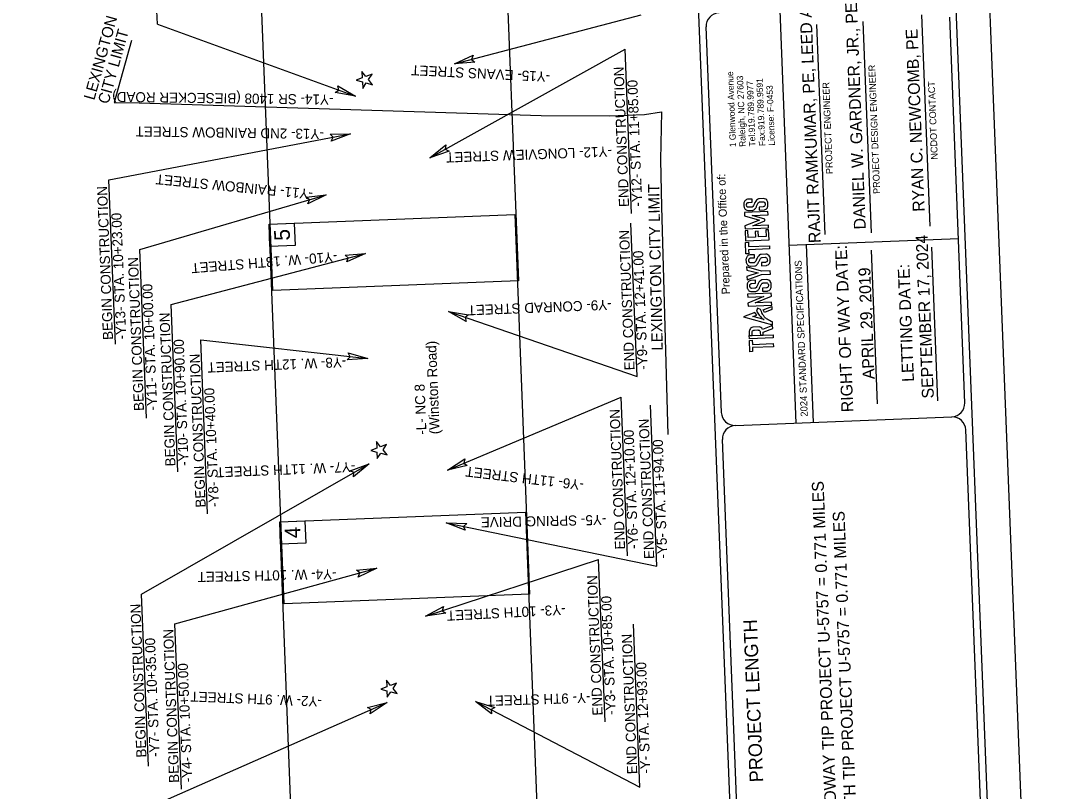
# Model space of a CAD drawing. Extents: x 1624323 to 1631382, y 753034 to 769560.
# Drawn here: x 1626744 to 1631382, y 761728 to 765176 of the extents above; entities that cross this region are included whole.
import ezdxf

# ---------------------------------------------------------------- set-up
doc = ezdxf.new("R2010")
doc.units = 0
for name, color, linetype in [('Old_Level_1', 7, 'Continuous'), ('Old_Level_2', 7, 'Continuous'), ('Prop Dimension', 7, 'Continuous'), ('Prop DSN Text', 7, 'Continuous'), ('Prop PHM City or Township Limit Line', 7, 'Continuous'), ('Prop RDY Traffic Signal CELL', 7, 'Continuous'), ('Prop Terminator CELL', 7, 'Continuous'), ('Sheet Data Field CELL', 7, 'Continuous'), ('Sheet Plot Border Outside CELL', 7, 'Continuous'), ('Sheet Title CELL', 7, 'Continuous')]:
    doc.layers.add(name, color=color, linetype=linetype)

msp = doc.modelspace()

# ---------------------------------------------------------------- linework, layer by layer
at = {"layer": 'Old_Level_1'}
for points in [[(1627871.9, 763968.6), (1627804.9, 765667.2), (1628904.1, 765710.6), (1628971.1, 764011.9)], [(1630017.6, 764363.7), (1630017, 764377.7), (1629996, 764376.8), (1629991.8, 764375.5), (1629988.3, 764373.6), (1629986, 764371.7), (1629984, 764369.4), (1629982.4, 764366.7), (1629981.4, 764364.1), (1629981.4, 764364.1), (1629980.3, 764361.3), (1629979.7, 764358.3), (1629979.3, 764356.3), (1629980, 764345.8), (1629980.6, 764342.6), (1629981.2, 764339.9), (1629982.8, 764337.1), (1629984.1, 764334.7), (1629986, 764332.4), (1629987.9, 764330.6), (1629990.2, 764329.2), (1629992.6, 764328.2), (1629996.9, 764326.8), (1630000, 764326.6), (1630019.2, 764327.4), (1630022, 764328.2), (1630025, 764329.7), (1630027.4, 764331.5), (1630029.2, 764333.4), (1630031.2, 764336.2), (1630033.2, 764339), (1630034.4, 764340.8), (1630035.7, 764343.8), (1630036.9, 764346.7), (1630038.4, 764349.2), (1630040, 764351.9), (1630041.5, 764355.1), (1630042.7, 764357.8), (1630044.5, 764360.5), (1630046.2, 764362.4), (1630047.6, 764364), (1630050.4, 764365), (1630052.2, 764365.7), (1630065.8, 764366), (1630068.7, 764365.1), (1630071.3, 764363.8), (1630073.2, 764361.8), (1630074.2, 764359.7), (1630074.7, 764357.7), (1630075.1, 764351.9), (1630074.6, 764349.9), (1630073.5, 764347.9), (1630072.4, 764345.8), (1630070.4, 764344.9), (1630068.5, 764344), (1630066.9, 764343.2), (1630048.1, 764342.3), (1630048.8, 764328.1), (1630071.2, 764329.3), (1630072.9, 764330.1), (1630078, 764331.9), (1630079.8, 764333), (1630081.6, 764334.6), (1630083.8, 764337), (1630084.9, 764338.9), (1630085.9, 764341.6), (1630086.2, 764342.5), (1630087.2, 764345.2), (1630087.4, 764348.4), (1630087.6, 764350.8), (1630086.7, 764363.8), (1630085.7, 764367.3), (1630083.3, 764372.2), (1630082.5, 764373.9), (1630077.5, 764377.4), (1630072.7, 764379.3), (1630068.4, 764380), (1630047.7, 764378.9), (1630044.8, 764378.7), (1630042.6, 764377.9), (1630040.5, 764376.6), (1630036, 764373.2), (1630032.8, 764368.8), (1630029.6, 764362.7), (1630027.1, 764358.1), (1630022.8, 764349.1), (1630019.6, 764344.4), (1630017.1, 764342.3), (1630015.4, 764341.8), (1630013.7, 764341.3), (1629999, 764340.9), (1629997.4, 764341.6), (1629995.8, 764342.3), (1629994.9, 764343.4), (1629993.6, 764344.7), (1629992.9, 764346.3), (1629992.2, 764347.8), (1629992.4, 764348.7), (1629991.9, 764348.8), (1629991.8, 764354.6), (1629992.4, 764356.3), (1629993, 764358), (1629993.6, 764359.7), (1629994.7, 764360.5), (1629996.3, 764361.7), (1629998, 764362.3), (1629999.6, 764362.9), (1630001.5, 764363)], [(1627922.1, 762567.4), (1627855.1, 764266), (1628954.3, 764309.4), (1629021.3, 762610.7)], [(1630049.2, 764283), (1629984.1, 764257.4), (1629985.2, 764244), (1630090.8, 764248.7), (1630090.2, 764261.5), (1630019.6, 764258.3), (1630073.2, 764280.2), (1630073, 764288.4), (1630017.1, 764304.8), (1630088, 764307.8), (1630087.4, 764321.6), (1629982.1, 764317.1), (1629982.7, 764303.2)], [(1627859.1, 764166.1), (1627855.1, 764266), (1627967.5, 764270.5), (1627971.5, 764170.6)], [(1629985.3, 764235.9), (1629987.1, 764191.2), (1630092.5, 764195.5), (1630090.7, 764240.6), (1630078.8, 764240.2), (1630080, 764209.7), (1630044.7, 764208.2), (1630043.6, 764233.7), (1630031.1, 764233.2), (1630032.1, 764207.5), (1629998.9, 764206.2), (1629997.7, 764236.5)], [(1629989.4, 764132.7), (1629987.4, 764183.8), (1629999.9, 764184.4), (1630000.7, 764165.5), (1630093.9, 764169.3), (1630094.5, 764155.1), (1630000.6, 764151.3), (1630001.4, 764133.4)], [(1630027.6, 764115.1), (1630027.1, 764129), (1630006, 764128.2), (1630001.8, 764126.8), (1629998.3, 764125), (1629996, 764123.1), (1629994, 764120.8), (1629992.4, 764118), (1629991.4, 764115.4), (1629991.4, 764115.4), (1629990.4, 764112.6), (1629989.8, 764109.7), (1629989.3, 764107.7), (1629990, 764097.1), (1629990.7, 764094), (1629991.2, 764091.2), (1629992.8, 764088.5), (1629994.2, 764086.1), (1629996, 764083.8), (1629998, 764082), (1630000.2, 764080.6), (1630002.7, 764079.5), (1630006.9, 764078.1), (1630010.1, 764078), (1630029.2, 764078.7), (1630032.1, 764079.5), (1630035, 764081), (1630037.4, 764082.9), (1630039.2, 764084.7), (1630041.2, 764087.5), (1630043.2, 764090.4), (1630044.5, 764092.1), (1630045.7, 764095.1), (1630047, 764098.1), (1630048.4, 764100.5), (1630050, 764103.2), (1630051.5, 764106.5), (1630052.7, 764109.2), (1630054.5, 764111.8), (1630056.2, 764113.8), (1630057.6, 764115.4), (1630060.5, 764116.4), (1630062.3, 764117), (1630075.8, 764117.3), (1630078.8, 764116.5), (1630081.4, 764115.1), (1630083.2, 764113.2), (1630084.3, 764111.1), (1630084.8, 764109), (1630085.1, 764103.2), (1630084.7, 764101.3), (1630083.6, 764099.2), (1630082.5, 764097.2), (1630080.5, 764096.3), (1630078.5, 764095.3), (1630076.9, 764094.6), (1630058.1, 764093.6), (1630058.8, 764079.5), (1630081.2, 764080.6), (1630082.9, 764081.4), (1630088.1, 764083.2), (1630089.8, 764084.4), (1630091.6, 764086), (1630093.8, 764088.4), (1630094.9, 764090.2), (1630095.9, 764092.9), (1630096.3, 764093.9), (1630097.3, 764096.5), (1630097.5, 764099.8), (1630097.6, 764102.2), (1630096.8, 764115.1), (1630095.8, 764118.7), (1630093.3, 764123.6), (1630092.5, 764125.2), (1630087.6, 764128.8), (1630082.7, 764130.6), (1630078.4, 764131.4), (1630057.7, 764130.3), (1630054.9, 764130.1), (1630052.6, 764129.2), (1630050.5, 764128), (1630046.1, 764124.5), (1630042.9, 764120.1), (1630039.6, 764114.1), (1630037.1, 764109.5), (1630032.8, 764100.5), (1630029.6, 764095.8), (1630027.1, 764093.7), (1630025.4, 764093.1), (1630023.7, 764092.6), (1630009, 764092.3), (1630007.5, 764093), (1630005.9, 764093.7), (1630004.9, 764094.7), (1630003.7, 764096.1), (1630003, 764097.6), (1630002.3, 764099.1), (1630002.4, 764100), (1630001.9, 764100.1), (1630001.8, 764105.9), (1630002.4, 764107.6), (1630003, 764109.3), (1630003.6, 764111), (1630004.7, 764111.9), (1630006.4, 764113), (1630008, 764113.7), (1630009.7, 764114.3), (1630011.5, 764114.3)], [(1629993.6, 764031.4), (1629994.2, 764016), (1630059.1, 764040.5), (1630098.7, 764042.2), (1630098, 764056.7), (1630058.8, 764054.9), (1629991.6, 764074.4), (1629992.7, 764059.4), (1630043.6, 764047.4)], [(1630032.2, 764001), (1630031.7, 764014.9), (1630010.6, 764014.1), (1630006.4, 764012.7), (1630002.9, 764010.9), (1630000.6, 764009), (1629998.6, 764006.7), (1629997, 764004), (1629996, 764001.3), (1629996, 764001.3), (1629995, 763998.5), (1629994.4, 763995.6), (1629994, 763993.6), (1629994.6, 763983), (1629995.3, 763979.9), (1629995.9, 763977.1), (1629997.4, 763974.4), (1629998.8, 763972), (1630000.6, 763969.7), (1630002.6, 763967.9), (1630004.8, 763966.5), (1630007.3, 763965.4), (1630011.5, 763964.1), (1630014.7, 763963.9), (1630033.8, 763964.6), (1630036.7, 763965.4), (1630039.6, 763966.9), (1630042, 763968.8), (1630043.8, 763970.7), (1630045.8, 763973.5), (1630047.8, 763976.3), (1630049.1, 763978.1), (1630050.3, 763981), (1630051.6, 763984), (1630053, 763986.4), (1630054.6, 763989.2), (1630056.1, 763992.4), (1630057.3, 763995.1), (1630059.1, 763997.8), (1630060.8, 763999.7), (1630062.2, 764001.3), (1630065.1, 764002.3), (1630066.9, 764002.9), (1630080.4, 764003.3), (1630083.4, 764002.4), (1630086, 764001), (1630087.8, 763999.1), (1630088.9, 763997), (1630089.4, 763995), (1630089.7, 763989.2), (1630089.3, 763987.2), (1630088.2, 763985.1), (1630087.1, 763983.1), (1630085.1, 763982.2), (1630083.1, 763981.2), (1630081.5, 763980.5), (1630062.7, 763979.5), (1630063.4, 763965.4), (1630085.8, 763966.5), (1630087.5, 763967.3), (1630092.7, 763969.2), (1630094.4, 763970.3), (1630096.3, 763971.9), (1630098.4, 763974.3), (1630099.5, 763976.2), (1630100.5, 763978.8), (1630100.9, 763979.8), (1630101.9, 763982.5), (1630102.1, 763985.7), (1630102.2, 763988.1), (1630101.4, 764001), (1630100.4, 764004.6), (1630097.9, 764009.5), (1630097.1, 764011.1), (1630092.2, 764014.7), (1630087.3, 764016.5), (1630083, 764017.3), (1630062.3, 764016.2), (1630059.5, 764016), (1630057.2, 764015.1), (1630055.1, 764013.9), (1630050.7, 764010.5), (1630047.5, 764006), (1630044.2, 764000), (1630041.7, 763995.4), (1630037.4, 763986.4), (1630034.2, 763981.7), (1630031.7, 763979.6), (1630030, 763979.1), (1630028.3, 763978.5), (1630013.6, 763978.2), (1630012.1, 763978.9), (1630010.5, 763979.6), (1630009.5, 763980.6), (1630008.3, 763982), (1630007.6, 763983.5), (1630006.9, 763985.1), (1630007, 763986), (1630006.6, 763986), (1630006.4, 763991.8), (1630007, 763993.5), (1630007.6, 763995.2), (1630008.2, 763996.9), (1630009.3, 763997.8), (1630011, 763999), (1630012.6, 763999.6), (1630014.3, 764000.2), (1630016.1, 764000.2)], [(1629998.9, 763898.6), (1630104.4, 763902.8), (1630103.9, 763916.3), (1630029.7, 763913.3), (1630103, 763943.2), (1630102.3, 763956.8), (1629996.5, 763952.5), (1629997, 763939.3), (1630069.4, 763942.3), (1629998.3, 763912.8)], [(1629977.7, 763850.7), (1630108.2, 763815.5), (1630107.7, 763828.9), (1630102.5, 763830.8), (1630095.3, 763834), (1630091.5, 763835.7), (1630088.1, 763837.8), (1630083.4, 763840.8), (1630080.5, 763842.7), (1630078, 763844.9), (1630075.6, 763847.1), (1630072.4, 763849.9), (1630070.7, 763852.3), (1630068.6, 763854.8), (1630066.6, 763858.1), (1630064.7, 763861), (1630061, 763868.2), (1630058.3, 763874.1), (1630054.5, 763883.9), (1630041.3, 763890.3), (1630036, 763876.9), (1630041.8, 763867.3), (1630047.6, 763859.1), (1630052.6, 763853.4), (1630055.3, 763850.3), (1630058.9, 763847.2), (1630062.4, 763844.2), (1630065.1, 763841.8), (1630069.1, 763839.7), (1630071.3, 763838.5), (1630020.1, 763852.4), (1630037.3, 763859.1), (1630029.2, 763870.3)], [(1630072, 763870.2), (1630066.9, 763881.6), (1630105.3, 763896.8), (1630105.3, 763884.1)], [(1630016.9, 763767.3), (1630016.3, 763781.7), (1630016.6, 763783.6), (1630017.4, 763786), (1630018.7, 763788.1), (1630020.3, 763789.5), (1630022.2, 763790.5), (1630023.8, 763791.3), (1630027.3, 763791.5), (1630042.3, 763792.1), (1630044.3, 763791.8), (1630047, 763791.4), (1630048.8, 763790.7), (1630050.5, 763789.6), (1630051.8, 763788), (1630052.8, 763785.5), (1630053.2, 763783.5), (1630053.5, 763781.5), (1630054.1, 763768.8), (1630066.8, 763769.4), (1630066.2, 763782.1), (1630109, 763798.1), (1630108.3, 763812.7), (1630063.3, 763794.9), (1630062.4, 763797.2), (1630059.8, 763800.3), (1630056.5, 763803.1), (1630052.6, 763805.1), (1630048.7, 763806.2), (1630047.6, 763806.1), (1630020, 763805.3), (1630015.5, 763803.9), (1630011.5, 763801.5), (1630008.8, 763798.9), (1630006.1, 763794.6), (1630004.9, 763790.4), (1630003.7, 763786.3), (1630003.8, 763783.8), (1630004.3, 763766.8)], [(1630004.9, 763752.8), (1630004.3, 763766.8), (1630110.5, 763771.1), (1630111.1, 763757.1)], [(1630007.1, 763694.6), (1630005.1, 763745.8), (1630017.6, 763746.3), (1630018.4, 763727.5), (1630111.6, 763731.3), (1630112.2, 763717.1), (1630018.3, 763713.3), (1630019, 763695.3)], [(1627969.8, 761235.6), (1627902.8, 762934.3), (1629002, 762977.6), (1629069, 761278.9)], [(1627906.8, 762834.4), (1627902.8, 762934.3), (1628015.2, 762938.7), (1628019.2, 762838.8)]]:
    msp.add_lwpolyline(points, close=True, dxfattribs=at)
at = {"layer": 'Prop Dimension'}
for p, q in [((1627355.4, 765160.5), (1627327.3, 765873.3)), ((1628685.4, 764982.9), (1629520.3, 765201.3)), ((1627355.4, 765160.5), (1628242, 764838.4)), ((1628574.3, 764562.4), (1629448.3, 765048.5)), ((1629477.3, 764313.8), (1629448.3, 765048.5)), ((1627138.5, 764464), (1628219.4, 764669.6)), ((1627167.5, 763728.5), (1627138.5, 764464)), ((1627276.7, 764152.9), (1628111.5, 764397)), ((1629501.8, 763583.3), (1629474.7, 764270.2)), ((1627306.5, 763397.2), (1627276.7, 764152.9)), ((1627417, 763906.2), (1628286.3, 764134.9)), ((1627446.5, 763157.5), (1627417, 763906.2)), ((1628657.5, 763874.5), (1629501.8, 763583.3)), ((1627579.9, 762969.9), (1627549.2, 763747.9)), ((1627549.2, 763747.9), (1628296.9, 763663.9)), ((1628653.4, 763165.2), (1629431.5, 763492.3)), ((1629459.5, 762781.9), (1629431.5, 763492.3)), ((1629590, 762735.8), (1629561.6, 763455.2)), ((1627284.9, 762610.3), (1628303.7, 763193.6)), ((1628647.7, 762929.4), (1629590, 762735.8)), ((1628555.1, 762511.5), (1629330.1, 762765.3)), ((1629358.8, 762038.6), (1629330.1, 762765.3)), ((1627434.3, 762477.3), (1628337.3, 762726.2)), ((1627315.2, 761840.5), (1627284.9, 762610.3)), ((1627463.5, 761737.5), (1627434.3, 762477.3)), ((1629515, 761746.8), (1629486.3, 762475.5)), ((1627107.9, 761564.7), (1628384.4, 762125.8)), ((1628778.3, 762130.4), (1629515, 761746.8))]:
    msp.add_line(p, q, dxfattribs=at)
at = {"layer": 'Prop PHM City or Township Limit Line'}
for points in [[(1627239.6, 765087.8), (1627162.4, 764809.9)], [(1627162.4, 764809.9), (1627274, 764808.5), (1629073.4, 764752.2), (1629377.1, 764749.7), (1629534.7, 764755.5), (1629611.7, 764767.7), (1629606.6, 764553.6), (1629611.3, 764343.2)], [(1629611.3, 764343.2), (1629639.1, 763324.1)]]:
    msp.add_lwpolyline(points, dxfattribs=at)
at = {"layer": 'Prop RDY Traffic Signal CELL'}
for points in [[(1628272.9, 764902), (1628274.1, 764873.2), (1628290.1, 764897.2), (1628317.9, 764889.3), (1628300, 764912), (1628316, 764936.1), (1628288.9, 764926), (1628271.1, 764948.7), (1628272.2, 764919.9), (1628245.1, 764909.8), (1628272.9, 764902)], [(1628338.1, 763245.8), (1628339.3, 763217), (1628355.3, 763241), (1628383.1, 763233.1), (1628365.2, 763255.8), (1628381.2, 763279.9), (1628354.1, 763269.8), (1628336.3, 763292.5), (1628337.4, 763263.7), (1628310.3, 763253.6), (1628338.1, 763245.8)], [(1628382.9, 762178.1), (1628384.1, 762149.3), (1628400.1, 762173.3), (1628427.9, 762165.4), (1628410, 762188.1), (1628426, 762212.1), (1628399, 762202.1), (1628381.1, 762224.8), (1628382.2, 762195.9), (1628355.1, 762185.9), (1628382.9, 762178.1)]]:
    msp.add_lwpolyline(points, dxfattribs=at)
at = {"layer": 'Prop Terminator CELL'}
for points in [[(1628776.4, 764990.7), (1628685.4, 764982.9), (1628768.9, 765021.3), (1628761.8, 765002.9)], [(1628162.7, 764883.7), (1628242, 764838.4), (1628151.4, 764854.2), (1628167.7, 764865.4)], [(1628128.1, 764668), (1628219.4, 764669.6), (1628133.5, 764636.9), (1628141.8, 764654.8)], [(1628660.5, 764592.6), (1628574.3, 764562.4), (1628645.7, 764620.4), (1628643.4, 764600.8)], [(1628020.7, 764386.6), (1628111.5, 764397), (1628029.1, 764356.3), (1628035.7, 764374.8)], [(1628195.4, 764127), (1628286.3, 764134.9), (1628202.9, 764096.4), (1628209.9, 764114.8)], [(1628737.5, 763830.5), (1628657.5, 763874.5), (1628748.3, 763860.1), (1628732.2, 763848.7)], [(1628209.2, 763689.3), (1628296.9, 763663.9), (1628205.1, 763658.1), (1628218.4, 763672.7)], [(1628217.9, 763162.4), (1628303.7, 763193.6), (1628233.1, 763134.8), (1628235.1, 763154.4)], [(1628742.4, 763185.8), (1628653.4, 763165.2), (1628730.7, 763215), (1628726.3, 763195.8)], [(1628732.8, 762896.1), (1628647.7, 762929.4), (1628739.6, 762926.9), (1628725.1, 762913.5)], [(1628246.4, 762717.3), (1628337.3, 762726.2), (1628254.3, 762686.7), (1628261.1, 762705.2)], [(1628645.5, 762524.8), (1628555.1, 762511.5), (1628636.2, 762554.9), (1628630.2, 762536.1)], [(1628295.9, 762103.3), (1628384.4, 762125.8), (1628308.2, 762074.4), (1628312.2, 762093.6)], [(1628851, 762075.1), (1628778.3, 762130.4), (1628866, 762102.8), (1628848.4, 762093.9)]]:
    msp.add_lwpolyline(points, close=True, dxfattribs=at)
at = {"layer": 'Sheet Plot Border Outside CELL'}
msp.add_lwpolyline([(1624322.9, 767519.9), (1624724.8, 757327.8), (1631382.3, 757590.3), (1630980.3, 767782.4)], close=True, dxfattribs=at)
at = {"layer": 'Sheet Title CELL'}
for p, q in [((1630025.6, 758943.2), (1629686.7, 767537.4)), ((1630140.3, 765221.6), (1630213, 763375.6)), ((1630551, 764226.1), (1630513.7, 765171.7)), ((1630813.6, 764256.4), (1630776.4, 765202.1)), ((1629879.3, 763423.1), (1629811.3, 765148)), ((1630343.1, 764220), (1630306.1, 765159)), ((1630181.6, 764171.8), (1630939.7, 764201.7)), ((1630258.9, 764174.8), (1630290.2, 763378.7)), ((1630549.8, 764149.9), (1630577, 763461.5)), ((1630819.7, 764163), (1630846.8, 763474.6)), ((1630267.9, 763945.4), (1630267.9, 763945.4)), ((1630563.5, 763805.6), (1630563.5, 763805.6)), ((1629942.2, 763364.9), (1630910.6, 763403.1)), ((1629974.8, 761002.1), (1629884.1, 763302))]:
    msp.add_line(p, q, dxfattribs=at)
for points in [[(1631188.8, 758655.6), (1630835.6, 767613)], [(1630968.7, 763466), (1630900.8, 765190.9)], [(1631064.2, 761045.1), (1630973.6, 763345)]]:
    msp.add_lwpolyline(points, dxfattribs=at)
for centre, start, end in [((1629871.5, 765150.4), 92.2582, 182.2582), ((1630907.9, 763463.7), 272.2582, 2.2582), ((1629939.5, 763425.5), 182.2582, 272.2582), ((1629944.3, 763304.4), 92.2582, 182.2582), ((1630912.7, 763342.6), 2.2582, 92.2582)]:
    msp.add_arc(centre, 60.6, start, end, dxfattribs=at)

# ---------------------------------------------------------------- texts
at = {"layer": 'Old_Level_2'}
for s, p in [('1 Glenwood Avenue', (1629945.1, 764610.3)), ('Raleigh, NC 27603', (1629988.6, 764612)), ('Tel:919.789.9977 ', (1630032.1, 764613.7)), ('Fax:919.789.9591', (1630075.6, 764615.4)), ('License: F-0453', (1630119.1, 764617.2))]:
    msp.add_text(s, height=28.179, rotation=92.2582, dxfattribs=at).set_placement(p)
at = {"layer": 'Prop DSN Text'}
for s, height, rotation, p in [('LEXINGTON', 50, 74.4686, (1627073.1, 764817.5)), ('CITY LIMIT', 50, 74.4686, (1627136.2, 764800)), ('-Y15- EVANS STREET', 45, 177.1852, (1629114.1, 764946.5)), ('END CONSTRUCTION', 45, 92.2582, (1629466.4, 764343.1)), ('-Y12- STA. 11+85.00', 45, 92.2582, (1629525.3, 764345.4)), ('-Y14- SR 1408 (BIESECKER ROAD)', 45, 179.2561, (1628143.6, 764844.8)), ('-Y13- 2ND RAINBOW STREET', 45, 179.1874, (1628100.9, 764691)), ('-Y12- LONGVIEW STREET', 45, 182.0964, (1629388.6, 764613.1)), ('-Y11- RAINBOW STREET', 45, 174.4018, (1628053.3, 764420.6)), ('BEGIN CONSTRUCTION', 45, 92.2582, (1627157.3, 763748.5)), ('LEXINGTON CITY LIMIT', 50, 91.2819, (1629617.2, 763700.5)), ('-Y13- STA. 10+23.00', 45, 92.2582, (1627216.3, 763750.8)), ('5', 70, 92.2582, (1627949.2, 764192.9)), ('END CONSTRUCTION', 45, 92.2582, (1629490.9, 763612.6)), ('BEGIN CONSTRUCTION', 45, 92.2582, (1627295.8, 763430.7)), ('-Y10- W. 13TH STREET', 45, 184.5479, (1628159.4, 764142.8)), ('-Y9- STA. 12+41.00', 45, 92.2582, (1629549.8, 763614.9)), ('-Y11- STA. 10+00.00', 45, 92.2582, (1627354.7, 763433)), ('-Y9- CONRAD STREET', 45, 182.2589, (1629387.5, 763927.8)), ('BEGIN CONSTRUCTION', 45, 92.2582, (1627436.6, 763182.8)), ('-Y10- STA. 10+90.00', 45, 92.2582, (1627495.5, 763185.2)), ('(Winston Road)', 45, 92.2582, (1628618.9, 763326.6)), ('BEGIN CONSTRUCTION', 45, 92.2582, (1627571.8, 762998.6)), ('-Y8- W. 12TH STREET', 45, 182.3088, (1628199.9, 763671.3)), ('-L- NC 8', 45, 92.2582, (1628559.9, 763324.3)), ('-Y8- STA. 10+40.00', 45, 92.2582, (1627630.8, 763000.9)), ('END CONSTRUCTION', 45, 92.2582, (1629448.5, 762811.2)), ('END CONSTRUCTION', 45, 92.2582, (1629579, 762768.1)), ('-Y6- STA. 12+10.00', 45, 92.2582, (1629507.5, 762813.6)), ('-Y5- STA. 11+94.00', 45, 92.2582, (1629637.9, 762770.4)), ('-Y7- W. 11TH STREET', 45, 182.2802, (1628239.8, 763202.3)), ('-Y6- 11TH STREET', 45, 173.256, (1629265.6, 763119.4)), ('-Y5- SPRING DRIVE', 45, 181.1407, (1629363.9, 762965.3)), ('4', 70, 92.258, (1627996.9, 762861.2)), ('-Y4- W. 10TH STREET', 45, 181.2524, (1628156.6, 762722.9)), ('END CONSTRUCTION', 45, 92.2582, (1629347.9, 762067.9)), ('-Y3- STA. 10+85.00', 45, 92.2582, (1629406.8, 762070.3)), ('BEGIN CONSTRUCTION', 45, 92.2582, (1627306.7, 761880.1)), ('-Y3- 10TH STREET', 45, 182.9208, (1629181, 762563.3)), ('BEGIN CONSTRUCTION', 45, 92.2582, (1627453.3, 761766.9)), ('-Y7- STA. 10+35.00', 45, 92.2582, (1627365.7, 761882.4)), ('END CONSTRUCTION', 45, 92.2582, (1629502.9, 761805.6)), ('-Y4- STA. 10+50.00', 45, 92.2582, (1627512.2, 761769.3)), ('-Y- STA. 12+93.00', 45, 92.2582, (1629561.9, 761807.9)), ('-Y2- W. 9TH STREET', 45, 177.7354, (1628092.6, 762151.8)), ('-Y- 9TH STREET', 45, 181.7963, (1629292.6, 762169.5))]:
    msp.add_text(s, height=height, rotation=rotation, dxfattribs=at).set_placement(p)
at = {"layer": 'Sheet Data Field CELL'}
for s, p in [('RAJIT RAMKUMAR, PE, LEED AP', (1630323.7, 764181.8)), ('DANIEL W. GARDNER, JR., PE', (1630525.7, 764242.9)), ('RYAN C. NEWCOMB, PE', (1630788.8, 764322.2)), ('SEPTEMBER 17, 2024', (1630830.2, 763486.8)), ('APRIL 29, 2019', (1630564.9, 763572.8)), ('LENGTH ROADWAY TIP PROJECT U-5757 = 0.771 MILES', (1630411.2, 761222.1)), ('TOTAL LENGTH TIP PROJECT U-5757 = 0.771 MILES', (1630499.3, 761225.6))]:
    msp.add_text(s, height=52.999, rotation=92.2582, dxfattribs=at).set_placement(p)
at = {"layer": 'Sheet Title CELL'}
for s, height, p in [('PROJECT DESIGN ENGINEER', 30.282, (1630589.9, 764401.6)), ('PROJECT ENGINEER', 30.282, (1630377.9, 764490.2)), ('NCDOT CONTACT', 30.282, (1630847.7, 764555.2)), ('Prepared in the Office of:', 36.338, (1629917.7, 763952.3)), ('RIGHT OF WAY DATE: ', 52.998, (1630469.9, 763425.4)), ('2024 STANDARD SPECIFICATIONS', 31.496, (1630265.8, 763404.9)), ('LETTING DATE:', 52.998, (1630741.3, 763561.3)), ('PROJECT LENGTH', 60.568, (1630066.6, 761770.1))]:
    msp.add_text(s, height=height, rotation=92.2582, dxfattribs=at).set_placement(p)

doc.saveas('drawing.dxf')
